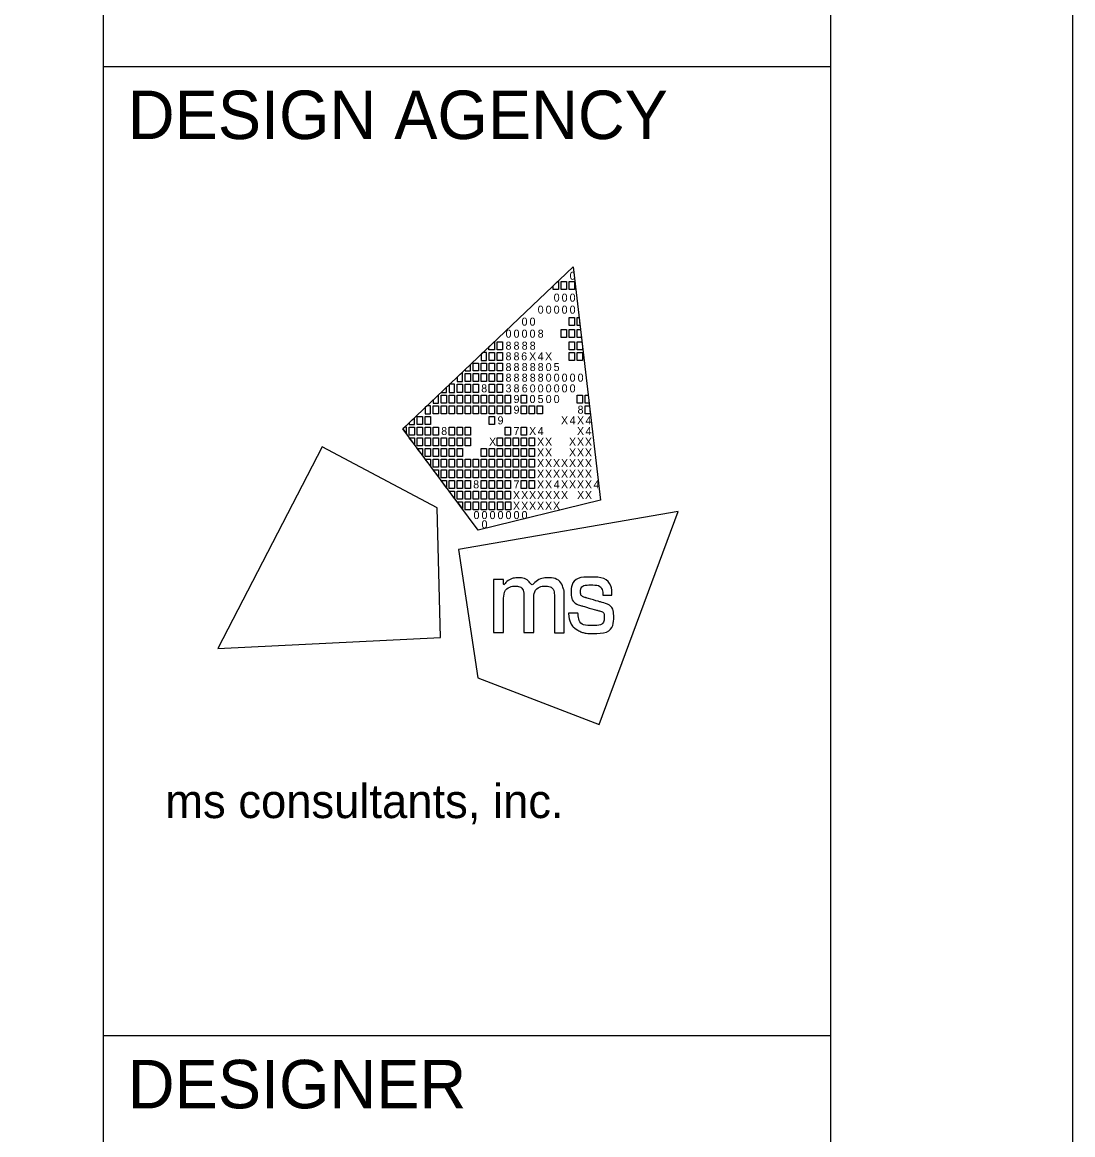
# Model space of a CAD drawing. Extents: x -0.7 to 34, y 0 to 22.
# Drawn here: x 31.832 to 34, y 2.295 to 4.591 of the extents above; entities that cross this region are included whole.
import ezdxf

# ---------------------------------------------------------------- set-up
doc = ezdxf.new("R2010")
doc.units = 0
for name, color, linetype in [('Default', 7, 'Continuous'), ('SH_Border', 7, 'Continuous'), ('SH_Cut_Line', 7, 'Continuous'), ('SH_Data', 7, 'Continuous')]:
    doc.layers.add(name, color=color, linetype=linetype)

msp = doc.modelspace()

# ---------------------------------------------------------------- linework, layer by layer
at = {"layer": 'Default'}
for p, q in [((32.6175, 3.7519), (32.9688, 4.0861)), ((32.9688, 4.0861), (32.9688, 4.0861)), ((32.9688, 4.0861), (33.0253, 3.6052)), ((32.773, 3.543), (32.6175, 3.7519)), ((33.0253, 3.6052), (32.773, 3.543))]:
    msp.add_line(p, q, dxfattribs=at)
for points in [[(32.9279, 4.0472), (32.9369, 4.0558), (32.9389, 4.0558), (32.9389, 4.0393), (32.9279, 4.0393)], [(32.9444, 4.0558), (32.9554, 4.0558), (32.9554, 4.0393), (32.9444, 4.0393)], [(32.9609, 4.0558), (32.9719, 4.0558), (32.9719, 4.0393), (32.9609, 4.0393)], [(32.9606, 3.9815), (32.9716, 3.9815), (32.9716, 3.965), (32.9606, 3.965)], [(32.9771, 3.9815), (32.9811, 3.9815), (32.983, 3.965), (32.9771, 3.965)], [(32.9441, 3.9567), (32.9551, 3.9567), (32.9551, 3.9402), (32.9441, 3.9402)], [(32.9606, 3.9567), (32.9716, 3.9567), (32.9716, 3.9402), (32.9606, 3.9402)], [(32.9771, 3.9567), (32.984, 3.9567), (32.9859, 3.9402), (32.9771, 3.9402)], [(32.7953, 3.9211), (32.8064, 3.9316), (32.8064, 3.9154), (32.7953, 3.9154)], [(32.8123, 3.9319), (32.8233, 3.9319), (32.8233, 3.9154), (32.8123, 3.9154)], [(32.9606, 3.9319), (32.9716, 3.9319), (32.9716, 3.9154), (32.9606, 3.9154)], [(32.9771, 3.9319), (32.9869, 3.9319), (32.9881, 3.9218), (32.9881, 3.9154), (32.9771, 3.9154)], [(32.7958, 3.9099), (32.8068, 3.9099), (32.8068, 3.8934), (32.7958, 3.8934)], [(32.8123, 3.9099), (32.8233, 3.9099), (32.8233, 3.8934), (32.8123, 3.8934)], [(32.9606, 3.9099), (32.9716, 3.9099), (32.9716, 3.8934), (32.9606, 3.8934)], [(32.9771, 3.9099), (32.9881, 3.9099), (32.9881, 3.8934), (32.9771, 3.8934)], [(32.7627, 3.8879), (32.7737, 3.8879), (32.7737, 3.8714), (32.7627, 3.8714)], [(32.7793, 3.8879), (32.7903, 3.8879), (32.7903, 3.8714), (32.7793, 3.8714)], [(32.7958, 3.8879), (32.8068, 3.8879), (32.8068, 3.8714), (32.7958, 3.8714)], [(32.8123, 3.8879), (32.8233, 3.8879), (32.8233, 3.8714), (32.8123, 3.8714)], [(32.7462, 3.8659), (32.7572, 3.8659), (32.7572, 3.8494), (32.7462, 3.8494)], [(32.7627, 3.8659), (32.7737, 3.8659), (32.7737, 3.8494), (32.7627, 3.8494)], [(32.7793, 3.8659), (32.7903, 3.8659), (32.7903, 3.8494), (32.7793, 3.8494)], [(32.7958, 3.8659), (32.8068, 3.8659), (32.8068, 3.8494), (32.7958, 3.8494)], [(32.8123, 3.8659), (32.8233, 3.8659), (32.8233, 3.8494), (32.8123, 3.8494)], [(32.7297, 3.8439), (32.7407, 3.8439), (32.7407, 3.8273), (32.7297, 3.8273)], [(32.7462, 3.8439), (32.7572, 3.8439), (32.7572, 3.8273), (32.7462, 3.8273)], [(32.7627, 3.8439), (32.7737, 3.8439), (32.7737, 3.8273), (32.7627, 3.8273)], [(32.7958, 3.8439), (32.8068, 3.8439), (32.8068, 3.8273), (32.7958, 3.8273)], [(32.8123, 3.8439), (32.8233, 3.8439), (32.8233, 3.8273), (32.8123, 3.8273)], [(32.6967, 3.8218), (32.7077, 3.8218), (32.7077, 3.8053), (32.6967, 3.8053)], [(32.7132, 3.8218), (32.7242, 3.8218), (32.7242, 3.8053), (32.7132, 3.8053)], [(32.7297, 3.8218), (32.7407, 3.8218), (32.7407, 3.8053), (32.7297, 3.8053)], [(32.7462, 3.8218), (32.7572, 3.8218), (32.7572, 3.8053), (32.7462, 3.8053)], [(32.7627, 3.8218), (32.7737, 3.8218), (32.7737, 3.8053), (32.7627, 3.8053)], [(32.7793, 3.8218), (32.7903, 3.8218), (32.7903, 3.8053), (32.7793, 3.8053)], [(32.7958, 3.8218), (32.8068, 3.8218), (32.8068, 3.8053), (32.7958, 3.8053)], [(32.8123, 3.8218), (32.8233, 3.8218), (32.8233, 3.8053), (32.8123, 3.8053)], [(32.8288, 3.8218), (32.8398, 3.8218), (32.8398, 3.8053), (32.8288, 3.8053)], [(32.8618, 3.8218), (32.8728, 3.8218), (32.8728, 3.8053), (32.8618, 3.8053)], [(32.9771, 3.8218), (32.9881, 3.8218), (32.9881, 3.8053), (32.9771, 3.8053)], [(32.9935, 3.8218), (32.9998, 3.8218), (33.0018, 3.8053), (32.9935, 3.8053)], [(32.6802, 3.7998), (32.6912, 3.7998), (32.6912, 3.7833), (32.6802, 3.7833)], [(32.6967, 3.7998), (32.7077, 3.7998), (32.7077, 3.7833), (32.6967, 3.7833)], [(32.7132, 3.7998), (32.7242, 3.7998), (32.7242, 3.7833), (32.7132, 3.7833)], [(32.7297, 3.7998), (32.7407, 3.7998), (32.7407, 3.7833), (32.7297, 3.7833)], [(32.7462, 3.7998), (32.7572, 3.7998), (32.7572, 3.7833), (32.7462, 3.7833)], [(32.7627, 3.7998), (32.7737, 3.7998), (32.7737, 3.7833), (32.7627, 3.7833)], [(32.7793, 3.7998), (32.7903, 3.7998), (32.7903, 3.7833), (32.7793, 3.7833)], [(32.7958, 3.7998), (32.8068, 3.7998), (32.8068, 3.7833), (32.7958, 3.7833)], [(32.8123, 3.7998), (32.8233, 3.7998), (32.8233, 3.7833), (32.8123, 3.7833)], [(32.8288, 3.7998), (32.8398, 3.7998), (32.8398, 3.7833), (32.8288, 3.7833)], [(32.8618, 3.7998), (32.8728, 3.7998), (32.8728, 3.7833), (32.8618, 3.7833)], [(32.8783, 3.7998), (32.8893, 3.7998), (32.8893, 3.7833), (32.8783, 3.7833)], [(32.8947, 3.7998), (32.9057, 3.7998), (32.9057, 3.7833), (32.8947, 3.7833)], [(32.9935, 3.7998), (33.0024, 3.7998), (33.0044, 3.7833), (32.9935, 3.7833)], [(32.6471, 3.7778), (32.6581, 3.7778), (32.6581, 3.7613), (32.6471, 3.7613)], [(32.6637, 3.7778), (32.6747, 3.7778), (32.6747, 3.7613), (32.6637, 3.7613)], [(32.7958, 3.7778), (32.8068, 3.7778), (32.8068, 3.7613), (32.7958, 3.7613)], [(32.6306, 3.7558), (32.6416, 3.7558), (32.6416, 3.7393), (32.6306, 3.7393)], [(32.6471, 3.7558), (32.6581, 3.7558), (32.6581, 3.7393), (32.6471, 3.7393)], [(32.6637, 3.7558), (32.6747, 3.7558), (32.6747, 3.7393), (32.6637, 3.7393)], [(32.6802, 3.7558), (32.6912, 3.7558), (32.6912, 3.7393), (32.6802, 3.7393)], [(32.7132, 3.7558), (32.7242, 3.7558), (32.7242, 3.7393), (32.7132, 3.7393)], [(32.7297, 3.7558), (32.7407, 3.7558), (32.7407, 3.7393), (32.7297, 3.7393)], [(32.7462, 3.7558), (32.7572, 3.7558), (32.7572, 3.7393), (32.7462, 3.7393)], [(32.8288, 3.7558), (32.8398, 3.7558), (32.8398, 3.7393), (32.8288, 3.7393)], [(32.8618, 3.7558), (32.8728, 3.7558), (32.8728, 3.7393), (32.8618, 3.7393)], [(32.6306, 3.7338), (32.6416, 3.7338), (32.6416, 3.72)], [(32.6471, 3.7338), (32.6581, 3.7338), (32.6581, 3.7173), (32.6471, 3.7173)], [(32.6637, 3.7338), (32.6747, 3.7338), (32.6747, 3.7173), (32.6637, 3.7173)], [(32.6802, 3.7338), (32.6912, 3.7338), (32.6912, 3.7173), (32.6802, 3.7173)], [(32.6967, 3.7338), (32.7077, 3.7338), (32.7077, 3.7173), (32.6967, 3.7173)], [(32.7132, 3.7338), (32.7242, 3.7338), (32.7242, 3.7173), (32.7132, 3.7173)], [(32.7297, 3.7338), (32.7407, 3.7338), (32.7407, 3.7173), (32.7297, 3.7173)], [(32.7462, 3.7338), (32.7572, 3.7338), (32.7572, 3.7173), (32.7462, 3.7173)], [(32.8123, 3.7338), (32.8233, 3.7338), (32.8233, 3.7173), (32.8123, 3.7173)], [(32.8288, 3.7338), (32.8398, 3.7338), (32.8398, 3.7173), (32.8288, 3.7173)], [(32.8453, 3.7338), (32.8563, 3.7338), (32.8563, 3.7173), (32.8453, 3.7173)], [(32.8618, 3.7338), (32.8728, 3.7338), (32.8728, 3.7173), (32.8618, 3.7173)], [(32.8783, 3.7338), (32.8893, 3.7338), (32.8893, 3.7173), (32.8783, 3.7173)], [(32.6471, 3.7117), (32.6581, 3.7117), (32.6581, 3.698)], [(32.6637, 3.7117), (32.6747, 3.7117), (32.6747, 3.6952), (32.6637, 3.6952)], [(32.6802, 3.7117), (32.6912, 3.7117), (32.6912, 3.6952), (32.6802, 3.6952)], [(32.6967, 3.7117), (32.7077, 3.7117), (32.7077, 3.6952), (32.6967, 3.6952)], [(32.7132, 3.7117), (32.7242, 3.7117), (32.7242, 3.6952), (32.7132, 3.6952)], [(32.7297, 3.7117), (32.7407, 3.7117), (32.7407, 3.6952), (32.7297, 3.6952)], [(32.7793, 3.7117), (32.7903, 3.7117), (32.7903, 3.6952), (32.7793, 3.6952)], [(32.7958, 3.7117), (32.8068, 3.7117), (32.8068, 3.6952), (32.7958, 3.6952)], [(32.8123, 3.7117), (32.8233, 3.7117), (32.8233, 3.6952), (32.8123, 3.6952)], [(32.8288, 3.7117), (32.8398, 3.7117), (32.8398, 3.6952), (32.8288, 3.6952)], [(32.8453, 3.7117), (32.8563, 3.7117), (32.8563, 3.6952), (32.8453, 3.6952)], [(32.8618, 3.7117), (32.8728, 3.7117), (32.8728, 3.6952), (32.8618, 3.6952)], [(32.8783, 3.7117), (32.8893, 3.7117), (32.8893, 3.6952), (32.8783, 3.6952)], [(32.6637, 3.6897), (32.6747, 3.6897), (32.6747, 3.676)], [(32.6747, 3.6897), (32.6747, 3.6897), (32.6747, 3.6897)], [(32.6802, 3.6897), (32.6912, 3.6897), (32.6912, 3.6732), (32.6802, 3.6732)], [(32.6967, 3.6897), (32.7077, 3.6897), (32.7077, 3.6732), (32.6967, 3.6732)], [(32.7132, 3.6897), (32.7242, 3.6897), (32.7242, 3.6732), (32.7132, 3.6732)], [(32.7297, 3.6897), (32.7407, 3.6897), (32.7407, 3.6732), (32.7297, 3.6732)], [(32.7462, 3.6897), (32.7572, 3.6897), (32.7572, 3.6732), (32.7462, 3.6732)], [(32.7627, 3.6897), (32.7737, 3.6897), (32.7737, 3.6732), (32.7627, 3.6732)], [(32.7793, 3.6897), (32.7903, 3.6897), (32.7903, 3.6732), (32.7793, 3.6732)], [(32.7958, 3.6897), (32.8068, 3.6897), (32.8068, 3.6732), (32.7958, 3.6732)], [(32.8123, 3.6897), (32.8233, 3.6897), (32.8233, 3.6732), (32.8123, 3.6732)], [(32.8288, 3.6897), (32.8398, 3.6897), (32.8398, 3.6732), (32.8288, 3.6732)], [(32.8453, 3.6897), (32.8563, 3.6897), (32.8563, 3.6732), (32.8453, 3.6732)], [(32.8618, 3.6897), (32.8728, 3.6897), (32.8728, 3.6732), (32.8618, 3.6732)], [(32.8783, 3.6897), (32.8893, 3.6897), (32.8893, 3.6732), (32.8783, 3.6732)], [(32.6802, 3.6677), (32.6912, 3.6677), (32.6912, 3.654)], [(32.6967, 3.6677), (32.7077, 3.6677), (32.7077, 3.6512), (32.6967, 3.6512)], [(32.7132, 3.6677), (32.7242, 3.6677), (32.7242, 3.6512), (32.7132, 3.6512)], [(32.7297, 3.6677), (32.7407, 3.6677), (32.7407, 3.6512), (32.7297, 3.6512)], [(32.7462, 3.6677), (32.7572, 3.6677), (32.7572, 3.6512), (32.7462, 3.6512)], [(32.7627, 3.6677), (32.7737, 3.6677), (32.7737, 3.6512), (32.7627, 3.6512)], [(32.7793, 3.6677), (32.7903, 3.6677), (32.7903, 3.6512), (32.7793, 3.6512)], [(32.7958, 3.6677), (32.8068, 3.6677), (32.8068, 3.6512), (32.7958, 3.6512)], [(32.8123, 3.6677), (32.8233, 3.6677), (32.8233, 3.6512), (32.8123, 3.6512)], [(32.8288, 3.6677), (32.8398, 3.6677), (32.8398, 3.6512), (32.8288, 3.6512)], [(32.8453, 3.6677), (32.8563, 3.6677), (32.8563, 3.6512), (32.8453, 3.6512)], [(32.8618, 3.6677), (32.8728, 3.6677), (32.8728, 3.6512), (32.8618, 3.6512)], [(32.8783, 3.6677), (32.8893, 3.6677), (32.8893, 3.6512), (32.8783, 3.6512)], [(32.7077, 3.6305), (32.6965, 3.6457), (32.7077, 3.6457)], [(32.7132, 3.6457), (32.7242, 3.6457), (32.7242, 3.6292), (32.7132, 3.6292)], [(32.7297, 3.6457), (32.7407, 3.6457), (32.7407, 3.6292), (32.7297, 3.6292)], [(32.7462, 3.6457), (32.7572, 3.6457), (32.7572, 3.6292), (32.7462, 3.6292)], [(32.7793, 3.6457), (32.7903, 3.6457), (32.7903, 3.6292), (32.7793, 3.6292)], [(32.7958, 3.6457), (32.8068, 3.6457), (32.8068, 3.6292), (32.7958, 3.6292)], [(32.8123, 3.6457), (32.8233, 3.6457), (32.8233, 3.6292), (32.8123, 3.6292)], [(32.8288, 3.6457), (32.8398, 3.6457), (32.8398, 3.6292), (32.8288, 3.6292)], [(32.8618, 3.6457), (32.8728, 3.6457), (32.8728, 3.6292), (32.8618, 3.6292)], [(32.8783, 3.6457), (32.8893, 3.6457), (32.8893, 3.6292), (32.8783, 3.6292)], [(32.724, 3.6082), (32.7132, 3.6237), (32.7242, 3.6237)], [(32.7297, 3.6237), (32.7407, 3.6237), (32.7407, 3.6072), (32.7297, 3.6072)], [(32.7462, 3.6237), (32.7572, 3.6237), (32.7572, 3.6072), (32.7462, 3.6072)], [(32.7627, 3.6237), (32.7737, 3.6237), (32.7737, 3.6072), (32.7627, 3.6072)], [(32.7793, 3.6237), (32.7903, 3.6237), (32.7903, 3.6072), (32.7793, 3.6072)], [(32.7958, 3.6237), (32.8068, 3.6237), (32.8068, 3.6072), (32.7958, 3.6072)], [(32.8123, 3.6237), (32.8233, 3.6237), (32.8233, 3.6072), (32.8123, 3.6072)], [(32.8288, 3.6237), (32.8398, 3.6237), (32.8398, 3.6072), (32.8288, 3.6072)], [(32.7302, 3.6017), (32.7407, 3.6017), (32.7408, 3.5875)], [(32.7463, 3.6017), (32.7573, 3.6017), (32.7573, 3.5852), (32.7463, 3.5852)], [(32.763, 3.6017), (32.774, 3.6017), (32.774, 3.5852), (32.763, 3.5852)], [(32.7794, 3.6017), (32.7904, 3.6017), (32.7904, 3.5852), (32.7794, 3.5852)], [(32.796, 3.6017), (32.807, 3.6017), (32.807, 3.5852), (32.796, 3.5852)], [(32.8129, 3.6017), (32.8239, 3.6017), (32.8239, 3.5851), (32.8129, 3.5851)], [(32.8296, 3.6017), (32.8406, 3.6017), (32.8406, 3.5851), (32.8296, 3.5851)]]:
    msp.add_lwpolyline(points, close=True, dxfattribs=at)
for points in [[(32.7903, 3.9099), (32.7836, 3.9099), (32.7793, 3.9058), (32.7793, 3.8934), (32.7903, 3.8934), (32.7903, 3.9099)], [(32.7572, 3.8849), (32.7462, 3.8744), (32.7462, 3.8714), (32.7572, 3.8714), (32.7572, 3.8849)], [(32.7407, 3.8691), (32.7297, 3.8587), (32.7297, 3.8494), (32.7407, 3.8494), (32.7407, 3.8691)], [(32.7077, 3.8377), (32.6968, 3.8273), (32.7077, 3.8273), (32.7077, 3.8377)], [(32.7242, 3.8439), (32.7141, 3.8439), (32.7132, 3.843), (32.7132, 3.8273), (32.7242, 3.8273), (32.7242, 3.8439)], [(32.6912, 3.822), (32.6802, 3.8115), (32.6802, 3.8053), (32.6912, 3.8053), (32.6912, 3.822)], [(32.6747, 3.7998), (32.6679, 3.7998), (32.6637, 3.7958), (32.6637, 3.7833), (32.6747, 3.7833), (32.6747, 3.7998)], [(32.6416, 3.7749), (32.6306, 3.7644), (32.6306, 3.7613), (32.6416, 3.7613), (32.6416, 3.7749)], [(32.6251, 3.7558), (32.6216, 3.7558), (32.6175, 3.7519), (32.6251, 3.7417), (32.6251, 3.7558)], [(32.4512, 3.7149), (32.2359, 3.2988), (32.6956, 3.3215), (32.6884, 3.5892), (32.4512, 3.7149)], [(33.0229, 3.1422), (33.1859, 3.5814), (32.7324, 3.5029), (32.7722, 3.2381), (33.0229, 3.1422)]]:
    msp.add_lwpolyline(points, dxfattribs=at)
for points in [[(32.8048, 3.3315), (32.8048, 3.3315), (32.8048, 3.4409), (32.8048, 3.4409), (32.8048, 3.4409), (32.8255, 3.4409), (32.8255, 3.4409), (32.8255, 3.4409), (32.8255, 3.4297), (32.8255, 3.4297), (32.8346, 3.4399), (32.8457, 3.4445), (32.8555, 3.4445), (32.8688, 3.4445), (32.8791, 3.4372), (32.8837, 3.4266), (32.8915, 3.4381), (32.905, 3.4446), (32.9166, 3.4446), (32.9325, 3.4446), (32.9451, 3.435), (32.9494, 3.4213), (32.9494, 3.4212), (32.9494, 3.4212), (32.9494, 3.4212), (32.9501, 3.419), (32.9506, 3.4172), (32.9506, 3.4071), (32.9506, 3.4071), (32.9506, 3.3314), (32.9506, 3.3314), (32.9506, 3.3314), (32.9303, 3.3314), (32.9303, 3.3314), (32.9303, 3.3314), (32.9303, 3.4048), (32.9303, 3.4048), (32.9303, 3.4201), (32.9219, 3.4274), (32.911, 3.4274), (32.8995, 3.4274), (32.8879, 3.4171), (32.8879, 3.4001), (32.8879, 3.4001), (32.8879, 3.3315), (32.8879, 3.3315), (32.8879, 3.3315), (32.8674, 3.3315), (32.8674, 3.3315), (32.8674, 3.3315), (32.8674, 3.4059), (32.8674, 3.4059), (32.8674, 3.4203), (32.8588, 3.4274), (32.8496, 3.4274), (32.8384, 3.4274), (32.8254, 3.417), (32.8254, 3.3962), (32.8254, 3.3962), (32.8254, 3.3315), (32.8254, 3.3315), (32.8254, 3.3315), (32.8048, 3.3315), (32.8048, 3.3315)], [(32.9595, 3.3709), (32.9595, 3.3709), (32.9595, 3.3717), (32.9595, 3.3717), (32.9595, 3.3717), (32.9603, 3.3717), (32.9603, 3.3717), (32.9603, 3.3717), (32.9783, 3.3717), (32.9783, 3.3717), (32.9783, 3.3717), (32.9789, 3.3717), (32.9789, 3.3717), (32.9789, 3.3717), (32.979, 3.371), (32.979, 3.371), (32.9803, 3.3554), (32.9887, 3.346), (33.009, 3.346), (33.0273, 3.346), (33.0333, 3.3554), (33.0333, 3.3631), (33.0333, 3.3732), (33.0256, 3.3758), (33.0175, 3.378), (33.0175, 3.378), (32.987, 3.3867), (32.987, 3.3867), (32.972, 3.3909), (32.9648, 3.4019), (32.9648, 3.4142), (32.9648, 3.4303), (32.9768, 3.4462), (33.0052, 3.4462), (33.0348, 3.4462), (33.0489, 3.4285), (33.0489, 3.4095), (33.0489, 3.4095), (33.0489, 3.4087), (33.0489, 3.4087), (33.0489, 3.4087), (33.0482, 3.4087), (33.0482, 3.4087), (33.0482, 3.4087), (33.0312, 3.4087), (33.0312, 3.4087), (33.0312, 3.4087), (33.0305, 3.4087), (33.0305, 3.4087), (33.0305, 3.4087), (33.0305, 3.4094), (33.0305, 3.4094), (33.0301, 3.4208), (33.0226, 3.43), (33.0056, 3.43), (32.9891, 3.43), (32.9843, 3.4218), (32.9843, 3.4157), (32.9843, 3.4108), (32.9869, 3.4059), (32.9959, 3.4033), (32.9959, 3.4033), (33.0255, 3.3948), (33.0255, 3.3948), (33.0462, 3.3889), (33.0527, 3.3777), (33.0527, 3.3639), (33.0527, 3.3462), (33.041, 3.3298), (33.0087, 3.3298), (32.9952, 3.3298), (32.9877, 3.3321), (32.9823, 3.3348), (32.969, 3.3414), (32.9609, 3.3536), (32.9595, 3.3709)]]:
    msp.add_open_spline(points, degree=3, dxfattribs=at)
at = {"layer": 'SH_Border'}
for p, q in [((32, 0.5), (32, 21.5)), ((32, 4.5), (33.5, 4.5)), ((32, 2.5), (33.5, 2.5))]:
    msp.add_line(p, q, dxfattribs=at)
msp.add_lwpolyline([(1.5, 21.5), (33.5, 21.5), (33.5, 0.5), (1.5, 0.5)], close=True, dxfattribs=at)
at = {"layer": 'SH_Cut_Line'}
msp.add_lwpolyline([(0, 0), (34, 0), (34, 22), (0, 22)], close=True, dxfattribs=at)
at = {"layer": 'SH_Data'}
msp.add_line((32.75, 3.5), (32.75, 3.5), dxfattribs=at)

# ---------------------------------------------------------------- texts
at = {"layer": 'Default'}
for s, p in [('0', (32.9617, 4.0597)), ('0', (32.9288, 4.0145)), ('0', (32.9452, 4.0145)), ('0', (32.9617, 4.0145)), ('0', (32.8958, 3.9897)), ('0', (32.9123, 3.9897)), ('0', (32.9288, 3.9897)), ('0', (32.9452, 3.9897)), ('0', (32.9617, 3.9897)), ('0', (32.8625, 3.965)), ('0', (32.879, 3.965)), ('0', (32.8295, 3.9402)), ('0', (32.846, 3.9402)), ('0', (32.8625, 3.9402)), ('0', (32.879, 3.9402)), ('8', (32.8958, 3.9402)), ('8', (32.8295, 3.9154)), ('8', (32.846, 3.9154)), ('8', (32.8628, 3.9154)), ('8', (32.8793, 3.9154)), ('8', (32.8295, 3.8934)), ('8', (32.846, 3.8934)), ('6', (32.8618, 3.8934)), ('X', (32.8781, 3.8934)), ('4', (32.8958, 3.8934)), ('X', (32.911, 3.8934)), ('8', (32.8295, 3.8713)), ('8', (32.846, 3.8713)), ('8', (32.8628, 3.8713)), ('8', (32.8794, 3.8713)), ('8', (32.8958, 3.8713)), ('0', (32.9123, 3.8713)), ('5', (32.9287, 3.8713)), ('8', (32.8295, 3.8494)), ('8', (32.846, 3.8494)), ('8', (32.8628, 3.8494)), ('8', (32.8794, 3.8494)), ('8', (32.8958, 3.8494)), ('0', (32.9123, 3.8494)), ('0', (32.9288, 3.8494)), ('0', (32.9452, 3.8494)), ('0', (32.9617, 3.8494)), ('0', (32.9782, 3.8494)), ('8', (32.7793, 3.8273)), ('3', (32.8295, 3.8273)), ('8', (32.846, 3.8273)), ('6', (32.8629, 3.8273)), ('0', (32.8793, 3.8273)), ('0', (32.8958, 3.8273)), ('0', (32.9123, 3.8273)), ('0', (32.9288, 3.8273)), ('0', (32.9452, 3.8273)), ('0', (32.9617, 3.8273)), ('9', (32.846, 3.8053)), ('0', (32.879, 3.8053)), ('5', (32.8957, 3.8053)), ('0', (32.9123, 3.8053)), ('0', (32.9288, 3.8053)), ('9', (32.846, 3.7833)), ('8', (32.9781, 3.7833)), ('9', (32.813, 3.7613)), ('X', (32.9439, 3.7613)), ('4', (32.9617, 3.7613)), ('X', (32.9769, 3.7613)), ('4', (32.9946, 3.7613)), ('8', (32.6967, 3.7393)), ('7', (32.846, 3.7393)), ('X', (32.8781, 3.7393)), ('4', (32.8958, 3.7393)), ('X', (32.9769, 3.7393)), ('4', (32.9946, 3.7393)), ('X', (32.7955, 3.7173)), ('X', (32.8945, 3.7173)), ('X', (32.911, 3.7173)), ('X', (32.9604, 3.7173)), ('X', (32.9769, 3.7173)), ('X', (32.9933, 3.7173)), ('X', (32.8945, 3.6952)), ('X', (32.911, 3.6952)), ('X', (32.9604, 3.6952)), ('X', (32.9769, 3.6952)), ('X', (32.9933, 3.6952)), ('X', (32.8945, 3.6732)), ('X', (32.911, 3.6732)), ('X', (32.9274, 3.6732)), ('X', (32.9439, 3.6732)), ('X', (32.9604, 3.6732)), ('X', (32.9769, 3.6732)), ('X', (32.9933, 3.6732)), ('X', (32.8945, 3.6512)), ('X', (32.911, 3.6512)), ('X', (32.9274, 3.6512)), ('X', (32.9439, 3.6512)), ('X', (32.9604, 3.6512)), ('X', (32.9769, 3.6512)), ('X', (32.9933, 3.6512)), ('8', (32.7627, 3.6292)), ('7', (32.846, 3.6292)), ('X', (32.8945, 3.6292)), ('X', (32.911, 3.6292)), ('4', (32.9288, 3.6292)), ('X', (32.9439, 3.6292)), ('X', (32.9604, 3.6292)), ('X', (32.9769, 3.6292)), ('X', (32.9933, 3.6292)), ('4', (33.0111, 3.6292)), ('X', (32.8447, 3.6072)), ('X', (32.8616, 3.6072)), ('X', (32.878, 3.6072)), ('X', (32.8945, 3.6072)), ('X', (32.911, 3.6072)), ('X', (32.9274, 3.6072)), ('X', (32.9439, 3.6072)), ('X', (32.9771, 3.6072)), ('X', (32.9933, 3.6072)), ('0', (32.7634, 3.5659)), ('0', (32.7799, 3.5659)), ('0', (32.7965, 3.5659)), ('0', (32.813, 3.5659)), ('0', (32.8295, 3.5659)), ('X', (32.8447, 3.5851)), ('0', (32.846, 3.5659)), ('X', (32.8616, 3.5851)), ('0', (32.8625, 3.5659)), ('X', (32.878, 3.5851)), ('X', (32.8945, 3.5851)), ('X', (32.911, 3.5851)), ('X', (32.9274, 3.5851)), ('0', (32.7799, 3.5467))]:
    msp.add_text(s, height=0.0165, rotation=360, dxfattribs=at).set_placement(p)
at = {"layer": 'SH_Border'}
msp.add_text('ms consultants, inc.', height=0.07, rotation=360, dxfattribs=at).set_placement((32.1273, 2.9489))
at = {"layer": 'SH_Data'}
for s, p in [('DESIGN AGENCY', (32.05, 4.35)), ('DESIGNER', (32.05, 2.35))]:
    msp.add_text(s, height=0.1, dxfattribs=at).set_placement(p)

doc.saveas('drawing.dxf')
